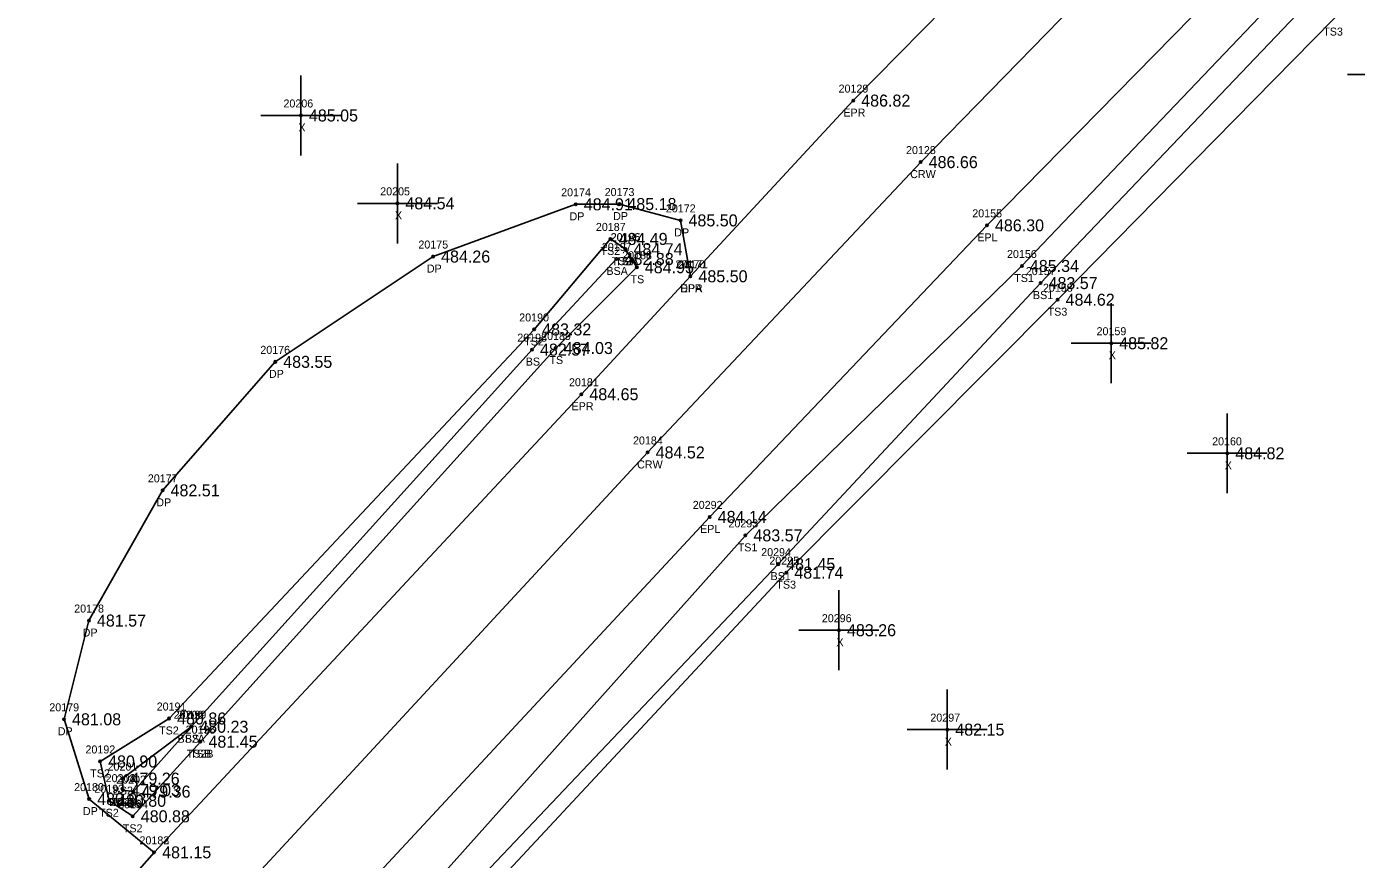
# Model space of a CAD drawing. Extents: x 1741010 to 1742139, y 749382 to 750625.
# Drawn here: x 1741801.4 to 1741967.6, y 750322.1 to 750426.2 of the extents above; entities that cross this region are included whole.
import ezdxf

# ---------------------------------------------------------------- set-up
doc = ezdxf.new("R2010")
doc.units = 0
for name, color, linetype in [('RD_DTM_BkLn1', 7, 'Continuous'), ('RD_DTM_BkLn2', 7, 'Continuous'), ('RD_DTM_BkLn_txCode', 7, 'Continuous'), ('RD_EX_Driveway', 7, 'Continuous'), ('RD_EX_Driveway_txCode', 7, 'Continuous'), ('RD_EX_Misc', 7, 'Continuous'), ('RD_EX_Misc_txCode', 7, 'Continuous'), ('RD_EX_Road', 7, 'Continuous'), ('RD_EX_Road_txCode', 7, 'Continuous'), ('RD_EX_TX_Driveway_ELEV', 7, 'Continuous'), ('RD_EX_TX_Misc_ELEV', 7, 'Continuous'), ('RD_EX_TX_Road_ELEV', 7, 'Continuous'), ('RD_HC_Survey_ELEV', 7, 'Continuous'), ('RD_HC_Survey_txCode', 7, 'Continuous'), ('RD_SMD_Locator', 7, 'Continuous')]:
    doc.layers.add(name, color=color, linetype=linetype)

msp = doc.modelspace()

# ---------------------------------------------------------------- linework, layer by layer
at = {"layer": 'RD_DTM_BkLn1'}
msp.add_lwpolyline([(1742095.1, 750579.47), (1742056.96, 750547.11), (1742019.74, 750514.22), (1741983.45, 750480.17), (1741948.01, 750445.01), (1741913.15, 750409.3), (1741879.03, 750372.99), (1741811.59, 750300.09), (1741743.65, 750226.52), (1741676.29, 750153.06), (1741642.32, 750115.53), (1741610.32, 750077.63)], dxfattribs=at)
at = {"layer": 'RD_DTM_BkLn2'}
for points in [[(1742105.6, 750567.48), (1742094.25, 750560.49), (1742091.64, 750555.7), (1742067.93, 750534.94), (1742031.73, 750501.95), (1741994.85, 750467.63), (1741959.82, 750432.06), (1741925.8, 750396.31), (1741891.25, 750362.62), (1741824.36, 750287.7), (1741756.44, 750214.6), (1741688.69, 750142.04), (1741655.55, 750103.43), (1741644.64, 750083.31), (1741626.06, 750060.3), (1741620, 750055.3), (1741614.97, 750059.12), (1741617.5, 750064.27), (1741619.23, 750067.96)], [(1742107.37, 750564.98), (1742099.21, 750558.66), (1742095.99, 750559.5), (1742095.15, 750554.39), (1742069.73, 750532.61), (1742034.06, 750499.81), (1741997.6, 750464.99), (1741961.88, 750429.54), (1741928.13, 750394.17), (1741895.34, 750359.02), (1741826.5, 750286.36), (1741758.73, 750213.29), (1741690.1, 750140.59), (1741658.36, 750099.77), (1741650.43, 750077.87), (1741632.9, 750061.59), (1741621.97, 750051.56), (1741618.99, 750048.78), (1741611.88, 750047.79)], [(1742108.6, 750563.87), (1742101.48, 750556.48), (1742102.57, 750548.5), (1742101.05, 750532.99), (1742105.06, 750513.92), (1742103.27, 750510.53), (1742100.54, 750509.6), (1742099.13, 750514.58), (1742095.78, 750530.6), (1742094.19, 750550.08), (1742071, 750531.59), (1742035.26, 750498.87), (1741998.91, 750463.73), (1741964.71, 750427.12), (1741930.26, 750392.09), (1741896.36, 750357.96), (1741828.15, 750284.74), (1741760.22, 750211.9), (1741691.37, 750138.81), (1741661.95, 750096.11), (1741655.14, 750072.69), (1741637.21, 750056.01), (1741627.61, 750046.43), (1741623.09, 750045.5)], [(1741876.26, 750398.41), (1741874.39, 750399.69), (1741864.85, 750388.37), (1741819.23, 750339.72), (1741810.61, 750334.35), (1741811.72, 750329.43), (1741814.69, 750327.49), (1741823.15, 750336.82)], [(1741876.26, 750398.41), (1741877.68, 750396.15), (1741867.55, 750386.05), (1741823.15, 750336.82)], [(1741875.15, 750397.19), (1741864.58, 750385.85), (1741822, 750338.69), (1741814.77, 750330.58), (1741813.45, 750330.76)], [(1741822, 750338.69), (1741813.41, 750332.2), (1741813.45, 750330.76)]]:
    msp.add_lwpolyline(points, dxfattribs=at)
at = {"layer": 'RD_EX_Driveway'}
msp.add_lwpolyline([(1741884.38, 750395.02), (1741883.14, 750402.01), (1741875.5, 750404.05), (1741870.05, 750404.02), (1741852.22, 750397.49), (1741832.49, 750384.32), (1741818.41, 750368.25), (1741809.21, 750351.97), (1741806.1, 750339.62), (1741809.24, 750329.64), (1741817.36, 750322.98)], dxfattribs=at)
at = {"layer": 'RD_EX_Misc'}
for p, q in [((1741835.7, 750410.13), (1741835.7, 750420.13)), ((1741966.49, 750420.27), (1741976.49, 750420.27)), ((1741830.7, 750415.13), (1741840.7, 750415.13)), ((1741847.76, 750399.14), (1741847.76, 750409.14)), ((1741842.76, 750404.14), (1741852.76, 750404.14)), ((1741936.96, 750381.65), (1741936.96, 750391.65)), ((1741931.96, 750386.65), (1741941.96, 750386.65)), ((1741951.47, 750367.88), (1741951.47, 750377.88)), ((1741946.47, 750372.88), (1741956.47, 750372.88)), ((1741902.94, 750345.76), (1741902.94, 750355.76)), ((1741897.94, 750350.76), (1741907.94, 750350.76)), ((1741916.48, 750333.33), (1741916.48, 750343.33)), ((1741911.48, 750338.33), (1741921.48, 750338.33))]:
    msp.add_line(p, q, dxfattribs=at)
at = {"layer": 'RD_EX_Road'}
for points in [[(1742095.24, 750593.27), (1742088.27, 750587.97), (1742078.23, 750580.89), (1742049.13, 750555.21), (1742012.94, 750522.73), (1741975.54, 750488.03), (1741940.71, 750452.82), (1741916.22, 750428.67), (1741904.72, 750416.99), (1741884.38, 750395.02), (1741870.75, 750380.27), (1741817.36, 750322.98), (1741803.89, 750307.66), (1741783.86, 750287.33), (1741735.44, 750234.07), (1741718.84, 750214.98), (1741710.25, 750205.58), (1741668.97, 750159.8), (1741635, 750122.49), (1741604.35, 750087.7), (1741600.63, 750085.47)], [(1742102.43, 750570.61), (1742093.26, 750562.71), (1742064.72, 750538.42), (1742027.92, 750505.65), (1741991.25, 750471.83), (1741956.32, 750436.98), (1741921.43, 750401.39), (1741886.79, 750364.93), (1741819.64, 750292.67), (1741751.78, 750219.01), (1741684.42, 750145.59), (1741650.98, 750108.5), (1741637.17, 750092.42), (1741621.17, 750073.94), (1741621.31, 750072.22), (1741619.24, 750070.27)]]:
    msp.add_lwpolyline(points, dxfattribs=at)
at = {"layer": 'RD_SMD_Locator'}
for centre in [(1741904.72, 750416.99), (1741835.7, 750415.13), (1741913.15, 750409.3), (1741847.76, 750404.14), (1741870.05, 750404.02), (1741875.5, 750404.05), (1741883.14, 750402.01), (1741921.43, 750401.39), (1741874.39, 750399.69), (1741852.22, 750397.49), (1741876.26, 750398.41), (1741876.26, 750398.41), (1741875.15, 750397.19), (1741877.68, 750396.15), (1741925.8, 750396.31), (1741884.38, 750395.02), (1741884.38, 750395.02), (1741928.13, 750394.17), (1741930.26, 750392.09), (1741864.85, 750388.37), (1741864.58, 750385.85), (1741867.55, 750386.05), (1741936.96, 750386.65), (1741832.49, 750384.32), (1741870.75, 750380.27), (1741879.03, 750372.99), (1741951.47, 750372.88), (1741818.41, 750368.25), (1741886.79, 750364.93), (1741891.25, 750362.62), (1741895.34, 750359.02), (1741896.36, 750357.96), (1741809.21, 750351.97), (1741902.94, 750350.76), (1741806.1, 750339.62), (1741819.23, 750339.72), (1741822, 750338.69), (1741822, 750338.69), (1741916.48, 750338.33), (1741823.15, 750336.82), (1741823.15, 750336.82), (1741810.61, 750334.35), (1741813.41, 750332.2), (1741809.24, 750329.64), (1741811.72, 750329.43), (1741813.45, 750330.76), (1741813.45, 750330.76), (1741814.77, 750330.58), (1741814.69, 750327.49), (1741817.36, 750322.98), (1741817.36, 750322.98)]:
    msp.add_circle(centre, 0.15, dxfattribs=at)

# ---------------------------------------------------------------- texts
at = {"layer": 'RD_DTM_BkLn_txCode'}
for s, p in [('TS3', (1741963.46, 750425.12)), ('20187', (1741872.56, 750400.69)), ('20186', (1741874.4, 750399.41)), ('20185', (1741874.43, 750399.41)), ('TS2', (1741873.15, 750397.69)), ('20197', (1741873.31, 750398.19)), ('20188', (1741875.85, 750397.15)), ('20156', (1741923.94, 750397.31)), ('BSA', (1741873.88, 750395.19)), ('TS2A', (1741874.53, 750396.41)), ('TSA', (1741874.98, 750396.41)), ('20157', (1741926.29, 750395.17)), ('TS', (1741876.89, 750394.15)), ('TS1', (1741924.84, 750394.31)), ('BS1', (1741927.18, 750392.17)), ('20158', (1741928.43, 750393.09)), ('TS3', (1741929.02, 750390.09)), ('20190', (1741862.98, 750389.37)), ('20198', (1741862.74, 750386.85)), ('20189', (1741865.72, 750387.05)), ('TS2', (1741863.61, 750386.37)), ('BS', (1741863.8, 750383.85)), ('TS', (1741866.76, 750384.05)), ('20293', (1741889.13, 750363.62)), ('TS1', (1741890.29, 750360.62)), ('20294', (1741893.22, 750360.02)), ('20295', (1741894.24, 750358.96)), ('BS1', (1741894.39, 750357.02)), ('TS3', (1741895.12, 750355.96)), ('20191', (1741817.68, 750340.72)), ('20200', (1741819.8, 750339.69)), ('20199', (1741820.16, 750339.69)), ('TS2', (1741817.98, 750337.72)), ('20196', (1741821.29, 750337.82)), ('20195', (1741821.31, 750337.82)), ('20192', (1741808.78, 750335.35)), ('BS2A', (1741820.28, 750336.69)), ('BS', (1741821.22, 750336.69)), ('TS2B', (1741821.43, 750334.82)), ('TSB', (1741821.88, 750334.82)), ('TS2', (1741809.37, 750332.35)), ('20201', (1741811.54, 750333.2)), ('20193', (1741809.89, 750330.43)), ('20203', (1741811.3, 750331.76)), ('20204', (1741811.3, 750331.76)), ('BS2', (1741812.18, 750330.2)), ('20202', (1741812.62, 750331.58)), ('BS2B', (1741811.75, 750328.76)), ('BSB', (1741812.2, 750328.76)), ('20194', (1741812.86, 750328.49)), ('BS', (1741813.99, 750328.58)), ('TS2', (1741810.48, 750327.43)), ('TS2', (1741813.45, 750325.49))]:
    msp.add_text(s, height=1, dxfattribs=at).set_placement(p)
at = {"layer": 'RD_EX_Driveway_txCode'}
for s, p in [('20174', (1741868.22, 750405.02)), ('20173', (1741873.66, 750405.05)), ('DP', (1741869.27, 750402.02)), ('DP', (1741874.72, 750402.05)), ('20172', (1741881.31, 750403.01)), ('DP', (1741882.36, 750400.01)), ('20175', (1741850.38, 750398.49)), ('DP', (1741851.44, 750395.49)), ('20171', (1741882.83, 750396.02)), ('DPA', (1741883.11, 750393.02)), ('20176', (1741830.63, 750385.32)), ('DP', (1741831.71, 750382.32)), ('20177', (1741816.57, 750369.25)), ('DP', (1741817.63, 750366.25)), ('20178', (1741807.37, 750352.97)), ('DP', (1741808.43, 750349.97)), ('20179', (1741804.26, 750340.62)), ('DP', (1741805.32, 750337.62)), ('20180', (1741807.36, 750330.64)), ('DP', (1741808.46, 750327.64)), ('20182', (1741815.53, 750323.98))]:
    msp.add_text(s, height=1, dxfattribs=at).set_placement(p)
at = {"layer": 'RD_EX_Misc_txCode'}
for s, p in [('20206', (1741833.52, 750416.13)), ('X', (1741835.39, 750413.13)), ('20205', (1741845.61, 750405.14)), ('X', (1741847.45, 750402.14)), ('20159', (1741935.13, 750387.65)), ('X', (1741936.65, 750384.65)), ('20160', (1741949.57, 750373.88)), ('X', (1741951.15, 750370.88)), ('20296', (1741900.8, 750351.76)), ('X', (1741902.63, 750348.76)), ('20297', (1741914.36, 750339.33)), ('X', (1741916.16, 750336.33))]:
    msp.add_text(s, height=1, dxfattribs=at).set_placement(p)
at = {"layer": 'RD_EX_Road_txCode'}
for s, p in [('20129', (1741902.89, 750417.99)), ('EPR', (1741903.49, 750414.99)), ('20155', (1741919.6, 750402.39)), ('EPL', (1741920.23, 750399.39)), ('20170', (1741882.51, 750396.02)), ('EPR', (1741883.15, 750393.02)), ('20181', (1741869.2, 750381.27)), ('EPR', (1741869.52, 750378.27)), ('20292', (1741884.67, 750365.93)), ('EPL', (1741885.58, 750362.93)), ('20183', (1741815.53, 750323.98))]:
    msp.add_text(s, height=1, dxfattribs=at).set_placement(p)
at = {"layer": 'RD_EX_TX_Driveway_ELEV'}
for s, p in [('484.91', (1741871.05, 750403.27)), ('485.18', (1741876.5, 750403.3)), ('485.50', (1741884.14, 750401.26)), ('484.26', (1741853.22, 750396.74)), ('485.50', (1741885.38, 750394.27)), ('483.55', (1741833.49, 750383.57)), ('482.51', (1741819.41, 750367.5)), ('481.57', (1741810.21, 750351.22)), ('481.08', (1741807.1, 750338.87)), ('480.93', (1741810.24, 750328.89)), ('481.15', (1741818.36, 750322.23))]:
    msp.add_text(s, height=1.5, dxfattribs=at).set_placement(p)
at = {"layer": 'RD_EX_TX_Misc_ELEV'}
for s, p in [('485.05', (1741836.7, 750414.38)), ('484.54', (1741848.76, 750403.39)), ('484.49', (1741875.39, 750398.94)), ('482.88', (1741876.15, 750396.44)), ('484.74', (1741877.26, 750397.66)), ('484.74', (1741877.26, 750397.66)), ('484.95', (1741878.68, 750395.4)), ('485.34', (1741926.8, 750395.56)), ('483.57', (1741929.13, 750393.42)), ('484.62', (1741931.26, 750391.34)), ('483.32', (1741865.85, 750387.62)), ('482.57', (1741865.58, 750385.1)), ('484.03', (1741868.55, 750385.3)), ('485.82', (1741937.96, 750385.9)), ('484.82', (1741952.47, 750372.13)), ('483.57', (1741892.25, 750361.87)), ('481.45', (1741896.34, 750358.27)), ('481.74', (1741897.36, 750357.21)), ('483.26', (1741903.94, 750350.01)), ('480.86', (1741820.23, 750338.97)), ('480.23', (1741823, 750337.94)), ('480.23', (1741823, 750337.94)), ('482.15', (1741917.48, 750337.58)), ('481.45', (1741824.15, 750336.07)), ('481.45', (1741824.15, 750336.07)), ('480.90', (1741811.61, 750333.6)), ('479.26', (1741814.41, 750331.45)), ('479.03', (1741814.45, 750330.01)), ('479.03', (1741814.45, 750330.01)), ('479.36', (1741815.77, 750329.83)), ('480.80', (1741812.72, 750328.68)), ('480.88', (1741815.69, 750326.74))]:
    msp.add_text(s, height=1.5, dxfattribs=at).set_placement(p)
at = {"layer": 'RD_EX_TX_Road_ELEV'}
for s, p in [('486.82', (1741905.72, 750416.24)), ('486.30', (1741922.43, 750400.64)), ('485.50', (1741885.38, 750394.27)), ('484.65', (1741871.75, 750379.52)), ('484.14', (1741887.79, 750364.18)), ('481.15', (1741818.36, 750322.23))]:
    msp.add_text(s, height=1.5, dxfattribs=at).set_placement(p)
at = {"layer": 'RD_HC_Survey_ELEV'}
for s, p in [('486.66', (1741914.15, 750408.55)), ('484.52', (1741880.03, 750372.24))]:
    msp.add_text(s, height=1.5, dxfattribs=at).set_placement(p)
at = {"layer": 'RD_HC_Survey_txCode'}
for s, p in [('20128', (1741911.32, 750410.3)), ('CRW', (1741911.84, 750407.3)), ('20184', (1741877.2, 750373.99)), ('CRW', (1741877.72, 750370.99))]:
    msp.add_text(s, height=1, dxfattribs=at).set_placement(p)

doc.saveas('drawing.dxf')
